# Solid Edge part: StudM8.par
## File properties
Title: Vis de fixation diamètre 8
Subject: Robinet tournant
Author: ptcarter
Keywords: Acheté
Comments: Diamètre 8x25/Symbole CHc
Template: NORMAL.PAR
Last saved by: ptcarter
Revision: 36
Application: Solid Edge
File Size: 0
Number of Sheets: 0
Number of Objects: 0
Category: Robinet
Manager: BU Mécanique
Company: Intergraph France
Quantité: 2
Accuracy: 0.99
Document Number: 16
Revision: A
Project Name: Robinet tournant
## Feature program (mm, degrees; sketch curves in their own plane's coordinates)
sketch for "unnamed Protrusion 1" plane through (0, 0, 0) normal (0, -1, 0) x-axis (1, 0, 0)
  circle centre (0, 0) radius 4
extrude "unnamed Protrusion 1" add finite 25 along -normal
sketch for "ExtrudedProtrusion_2" plane through (0, 0, 0) normal (0, -1, 0) x-axis (1, 0, 0)
  line (3.7528, 6.5) -> (-3.7528, 6.5)
  line (-3.7528, 6.5) -> (-7.5056, 0)
  line (-7.5056, 0) -> (-3.7528, -6.5)
  line (-3.7528, -6.5) -> (3.7528, -6.5)
  line (3.7528, -6.5) -> (7.5056, 0)
  line (7.5056, 0) -> (3.7528, 6.5)
extrude "ExtrudedProtrusion_2" add finite 4 along +normal
chamfer "unnamed Chamfer 1"
sketch for "ExtrudedProtrusion_3" plane through (0, -4, 0) normal (0, -1, 0) x-axis (1, 0, 0)
extrude "ExtrudedProtrusion_3" add finite 12 along +normal
chamfer "Chamfer_4" setback 0.5
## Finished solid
Body 1: solid body, 14 faces, 24 edges, 12 vertices.
  Faces by surface: plane 10, cone 2, cylinder 2
  Edges by curve: line 18, circle 6
Bounding box of the edges (mm): 15.011 x 41.000 x 13.000, from (-7.5056, -16, -6.5) to (7.5056, 25, 6.5).
Cylindrical faces by radius (mm): R4 x2
Conical faces (half-angle, radius in mm at the cone's reference point): 45 deg R3.5 x2
Planar faces by outward normal: +y 2, +z 1, -y 2, -z 1, oblique 4
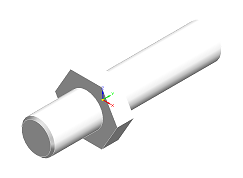
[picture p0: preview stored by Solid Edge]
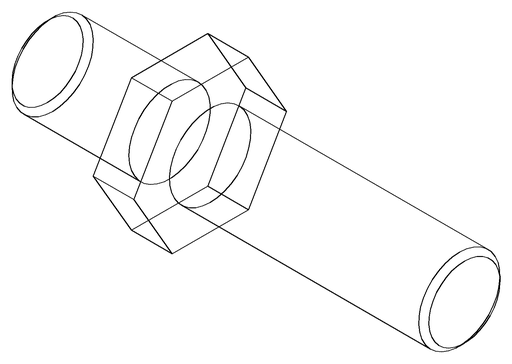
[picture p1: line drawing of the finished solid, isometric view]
